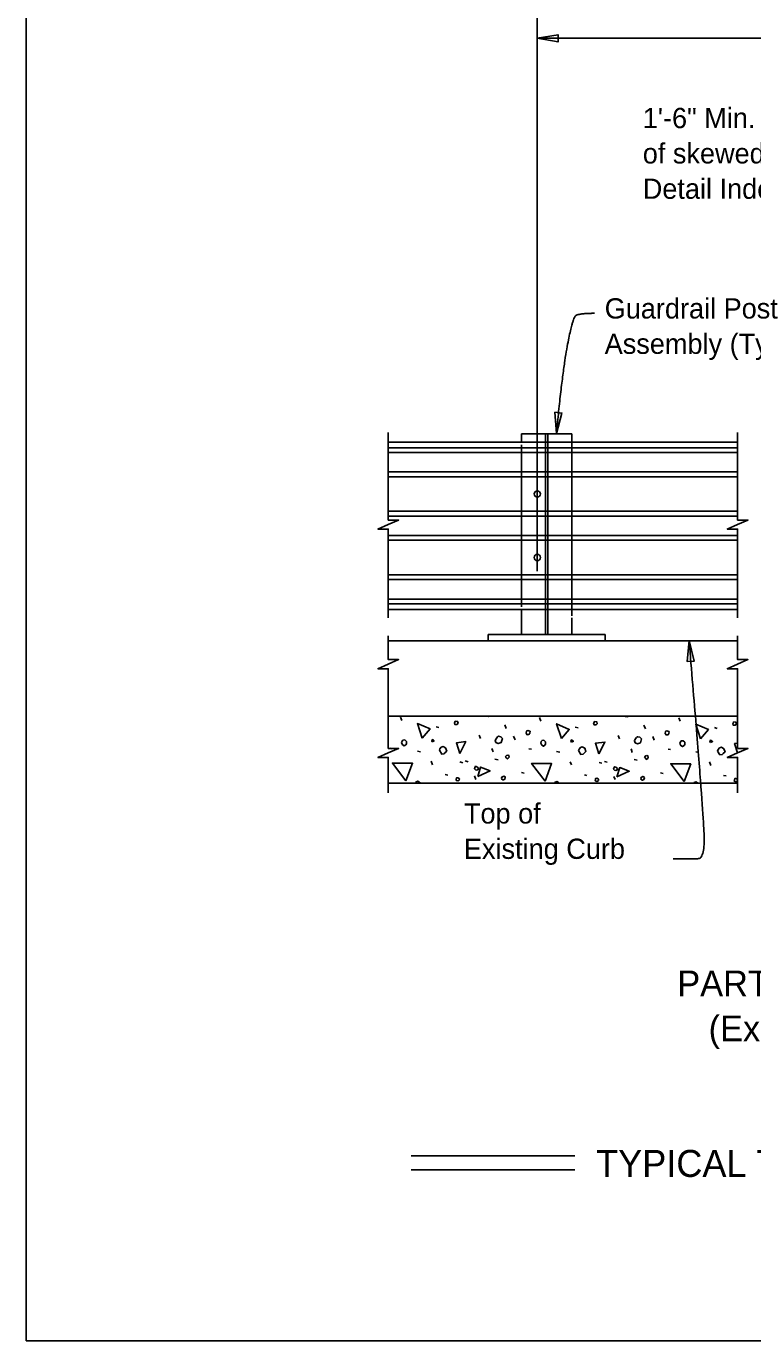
# Model space of a CAD drawing. Extents: x 0 to 41.1, y 0 to 25.9.
# Drawn here: x 0 to 7.23, y 0 to 13.09 of the extents above; entities that cross this region are included whole.
import ezdxf

# ---------------------------------------------------------------- set-up
doc = ezdxf.new("R2010")
doc.units = 0
for name, color, linetype in [('Dimension', 7, 'Continuous'), ('ExistSuperStruct', 7, 'Continuous'), ('Miscellaneous', 7, 'Continuous'), ('Miscellaneous1', 7, 'Continuous'), ('SteelMisc', 7, 'Continuous'), ('SteelMisc_h', 7, 'Continuous'), ('TextStructures', 7, 'Continuous')]:
    doc.layers.add(name, color=color, linetype=linetype)

msp = doc.modelspace()

# ---------------------------------------------------------------- linework, layer by layer
at = {"layer": 'Dimension'}
for p, q in [((5.085, 7.662), (5.085, 21.669)), ((5.459, 1.842), (3.831, 1.842)), ((5.459, 1.7), (3.831, 1.7))]:
    msp.add_line(p, q, dxfattribs=at)
for points in [[(5.085, 12.97), (11.216, 12.97), (11.216, 13.073), (11.261, 12.97), (11.306, 12.866), (11.306, 12.97), (17.272, 12.97)], [(3.602, 7.199), (3.602, 8.082), (3.499, 8.082), (3.602, 8.127), (3.705, 8.172), (3.602, 8.172), (3.602, 9.045)], [(7.079, 7.199), (7.079, 8.082), (6.976, 8.082), (7.079, 8.127), (7.182, 8.172), (7.079, 8.172), (7.079, 9.045)], [(3.602, 6.222), (3.602, 6.692), (3.499, 6.692), (3.602, 6.737), (3.705, 6.782), (3.602, 6.782), (3.602, 7.02)], [(7.079, 6.222), (7.079, 6.692), (6.976, 6.692), (7.079, 6.737), (7.182, 6.782), (7.079, 6.782), (7.079, 7.02)], [(3.602, 5.457), (3.602, 5.808), (3.499, 5.808), (3.602, 5.853), (3.705, 5.898), (3.602, 5.898), (3.602, 6.222)], [(7.079, 5.457), (7.079, 5.808), (6.976, 5.808), (7.079, 5.853), (7.182, 5.898), (7.079, 5.898), (7.079, 6.222)]]:
    msp.add_lwpolyline(points, dxfattribs=at)
for points in [[(5.085, 12.97), (5.293, 12.934), (5.293, 13.005)], [(5.275, 9.034), (5.33, 9.238), (5.26, 9.245)], [(6.596, 6.972), (6.578, 6.762), (6.648, 6.768)]]:
    msp.add_lwpolyline(points, close=True, dxfattribs=at)
for points in [[(5.654, 10.231), (5.491, 10.231), (5.438, 10.178), (5.34, 9.691), (5.275, 9.034)], [(6.439, 4.8), (6.622, 4.8), (6.746, 4.8), (6.746, 5.193), (6.596, 6.972)]]:
    msp.add_open_spline(points, degree=2, dxfattribs=at)
at = {"layer": 'ExistSuperStruct'}
for p, q in [((7.079, 6.97), (3.602, 6.97)), ((3.602, 6.22), (7.079, 6.22)), ((7.079, 5.553), (3.602, 5.553))]:
    msp.add_line(p, q, dxfattribs=at)
at = {"layer": 'Miscellaneous'}
for p, q in [((3.738, 6.175), (3.724, 6.21)), ((5.122, 6.171), (5.108, 6.207)), ((6.507, 6.168), (6.493, 6.203)), ((4.078, 6.112), (4.106, 6.105)), ((4.52, 5.996), (4.506, 6.031)), ((4.776, 6.096), (4.762, 6.132)), ((5.463, 6.109), (5.491, 6.102)), ((5.905, 5.992), (5.891, 6.027)), ((6.161, 6.093), (6.147, 6.128)), ((6.848, 6.105), (6.876, 6.098)), ((3.617, 5.899), (3.642, 5.895)), ((4.646, 5.863), (4.633, 5.897)), ((4.864, 5.984), (4.85, 6.019)), ((5.002, 5.895), (5.027, 5.892)), ((6.03, 5.859), (6.018, 5.893)), ((6.249, 5.98), (6.235, 6.016)), ((6.387, 5.892), (6.412, 5.888)), ((3.893, 5.871), (3.923, 5.865)), ((4.042, 5.736), (4.029, 5.77)), ((4.316, 5.763), (4.344, 5.756)), ((4.368, 5.773), (4.396, 5.766)), ((4.664, 5.791), (4.695, 5.786)), ((5.278, 5.867), (5.308, 5.862)), ((5.426, 5.733), (5.414, 5.766)), ((5.7, 5.759), (5.729, 5.752)), ((5.753, 5.769), (5.781, 5.762)), ((6.049, 5.788), (6.079, 5.782)), ((6.663, 5.864), (6.693, 5.858)), ((6.811, 5.729), (6.799, 5.763)), ((4.169, 5.637), (4.196, 5.632)), ((4.928, 5.659), (4.954, 5.653)), ((5.554, 5.634), (5.58, 5.629)), ((6.313, 5.655), (6.339, 5.65)), ((6.938, 5.63), (6.965, 5.625)), ((4.474, 5.59), (4.462, 5.624)), ((5.859, 5.587), (5.846, 5.62))]:
    msp.add_line(p, q, dxfattribs=at)
for points in [[(4.266, 6.137), (4.287, 6.137), (4.297, 6.148), (4.292, 6.167), (4.269, 6.169), (4.266, 6.158), (4.26, 6.149), (4.266, 6.137), (4.262, 6.141)], [(4.576, 6.22), (4.577, 6.218), (4.598, 6.215), (4.601, 6.22)], [(5.65, 6.133), (5.671, 6.133), (5.682, 6.144), (5.677, 6.164), (5.654, 6.165), (5.65, 6.155), (5.645, 6.146), (5.65, 6.133), (5.647, 6.137)], [(5.959, 6.22), (5.961, 6.215), (5.983, 6.211), (5.987, 6.22)], [(7.035, 6.13), (7.056, 6.13), (7.067, 6.141), (7.061, 6.16), (7.038, 6.162), (7.035, 6.151), (7.03, 6.142), (7.035, 6.13), (7.031, 6.133)], [(3.941, 6), (3.893, 6.146), (4.019, 6.092), (3.941, 6)], [(4.974, 6.051), (4.983, 6.035), (5.002, 6.037), (5.011, 6.049), (5.013, 6.069), (5, 6.074), (4.992, 6.076), (4.981, 6.072), (4.977, 6.069), (4.974, 6.051)], [(5.326, 5.996), (5.278, 6.143), (5.403, 6.088), (5.326, 5.996)], [(6.359, 6.047), (6.367, 6.032), (6.387, 6.033), (6.396, 6.046), (6.397, 6.065), (6.385, 6.07), (6.376, 6.072), (6.366, 6.069), (6.362, 6.065), (6.359, 6.047)], [(6.71, 5.993), (6.663, 6.139), (6.788, 6.085), (6.71, 5.993)], [(3.734, 5.956), (3.745, 5.934), (3.762, 5.924), (3.777, 5.934), (3.784, 5.945), (3.784, 5.966), (3.768, 5.982), (3.748, 5.98), (3.739, 5.971), (3.734, 5.956)], [(4.04, 5.964), (4.059, 5.973), (4.052, 5.98), (4.04, 5.986), (4.035, 5.973), (4.04, 5.964)], [(4.111, 5.88), (4.134, 5.842), (4.157, 5.844), (4.165, 5.853), (4.185, 5.872), (4.173, 5.903), (4.148, 5.917), (4.13, 5.91), (4.116, 5.895), (4.111, 5.88)], [(4.313, 5.849), (4.28, 5.953), (4.373, 5.966), (4.313, 5.849)], [(4.674, 5.958), (4.697, 5.946), (4.727, 5.958), (4.739, 5.996), (4.722, 6.013), (4.699, 6.019), (4.688, 6.012), (4.676, 5.992), (4.667, 5.976), (4.674, 5.958)], [(5.119, 5.952), (5.129, 5.931), (5.147, 5.92), (5.161, 5.931), (5.168, 5.941), (5.168, 5.963), (5.152, 5.979), (5.133, 5.977), (5.124, 5.968), (5.119, 5.952)], [(5.425, 5.961), (5.444, 5.97), (5.437, 5.977), (5.425, 5.982), (5.419, 5.97), (5.425, 5.961)], [(5.495, 5.876), (5.518, 5.839), (5.541, 5.841), (5.55, 5.849), (5.57, 5.869), (5.557, 5.899), (5.532, 5.913), (5.515, 5.906), (5.501, 5.892), (5.495, 5.876)], [(5.698, 5.845), (5.664, 5.95), (5.758, 5.962), (5.698, 5.845)], [(6.059, 5.955), (6.082, 5.943), (6.112, 5.955), (6.124, 5.992), (6.106, 6.01), (6.083, 6.015), (6.073, 6.008), (6.06, 5.989), (6.052, 5.973), (6.059, 5.955)], [(6.503, 5.948), (6.514, 5.927), (6.532, 5.917), (6.546, 5.927), (6.553, 5.938), (6.553, 5.959), (6.537, 5.975), (6.518, 5.973), (6.509, 5.964), (6.503, 5.948)], [(6.809, 5.957), (6.829, 5.966), (6.822, 5.973), (6.809, 5.979), (6.804, 5.966), (6.809, 5.957)], [(6.88, 5.872), (6.903, 5.835), (6.926, 5.837), (6.935, 5.846), (6.954, 5.865), (6.942, 5.895), (6.917, 5.91), (6.899, 5.903), (6.885, 5.888), (6.88, 5.872)], [(7.079, 5.853), (7.049, 5.946), (7.079, 5.95)], [(4.776, 5.804), (4.786, 5.793), (4.797, 5.8), (4.804, 5.811), (4.801, 5.828), (4.792, 5.83), (4.779, 5.828), (4.769, 5.818), (4.776, 5.804)], [(6.161, 5.8), (6.171, 5.789), (6.182, 5.796), (6.189, 5.807), (6.185, 5.825), (6.176, 5.827), (6.164, 5.825), (6.153, 5.814), (6.161, 5.8)], [(3.778, 5.575), (3.644, 5.752), (3.844, 5.751), (3.778, 5.575)], [(4.471, 5.684), (4.483, 5.683), (4.495, 5.688), (4.499, 5.699), (4.494, 5.707), (4.483, 5.715), (4.471, 5.72), (4.464, 5.706), (4.46, 5.695), (4.471, 5.684)], [(4.493, 5.62), (4.521, 5.712), (4.615, 5.674), (4.493, 5.62)], [(5.163, 5.572), (5.029, 5.749), (5.228, 5.747), (5.163, 5.572)], [(5.855, 5.681), (5.868, 5.679), (5.88, 5.684), (5.884, 5.695), (5.878, 5.704), (5.868, 5.711), (5.855, 5.716), (5.848, 5.702), (5.845, 5.692), (5.855, 5.681)], [(5.878, 5.616), (5.906, 5.708), (6, 5.671), (5.878, 5.616)], [(6.548, 5.568), (6.413, 5.745), (6.613, 5.743), (6.548, 5.568)], [(3.919, 5.553), (3.92, 5.554), (3.911, 5.563), (3.895, 5.572), (3.879, 5.567), (3.875, 5.553)], [(4.277, 5.579), (4.296, 5.574), (4.309, 5.583), (4.31, 5.595), (4.307, 5.598), (4.293, 5.606), (4.28, 5.604), (4.279, 5.591), (4.277, 5.579)], [(4.741, 5.584), (4.748, 5.584), (4.762, 5.591), (4.767, 5.607), (4.765, 5.616), (4.751, 5.623), (4.733, 5.613), (4.73, 5.602), (4.733, 5.591), (4.741, 5.584)], [(5.302, 5.553), (5.296, 5.56), (5.28, 5.568), (5.264, 5.563), (5.26, 5.553)], [(5.662, 5.575), (5.681, 5.57), (5.693, 5.579), (5.695, 5.591), (5.692, 5.595), (5.677, 5.602), (5.665, 5.6), (5.663, 5.588), (5.662, 5.575)], [(6.125, 5.581), (6.132, 5.581), (6.146, 5.588), (6.152, 5.604), (6.15, 5.613), (6.136, 5.62), (6.118, 5.609), (6.115, 5.598), (6.118, 5.588), (6.125, 5.581)], [(6.683, 5.553), (6.68, 5.556), (6.664, 5.565), (6.648, 5.56), (6.646, 5.553)], [(7.079, 5.589), (7.076, 5.591), (7.062, 5.598), (7.05, 5.597), (7.048, 5.584), (7.046, 5.572)], [(7.046, 5.572), (7.066, 5.567), (7.078, 5.575), (7.079, 5.582)]]:
    msp.add_lwpolyline(points, dxfattribs=at)
at = {"layer": 'Miscellaneous1'}
msp.add_lwpolyline([(0, 25.946), (41.051, 25.946), (41.051, 0), (0, 0)], close=True, dxfattribs=at)
at = {"layer": 'SteelMisc'}
for p, q in [((4.929, 9.032), (5.429, 9.032)), ((4.929, 9.032), (4.929, 8.949)), ((3.602, 8.949), (7.079, 8.949)), ((7.079, 8.893), (3.602, 8.893)), ((7.079, 8.845), (3.602, 8.845)), ((7.079, 8.652), (3.602, 8.652)), ((7.079, 8.604), (3.602, 8.604)), ((7.079, 8.26), (3.602, 8.26)), ((7.079, 8.212), (3.602, 8.212)), ((7.079, 8.019), (3.602, 8.019)), ((7.079, 7.971), (3.602, 7.971)), ((7.079, 7.627), (3.602, 7.627)), ((7.079, 7.579), (3.602, 7.579)), ((7.079, 7.386), (3.602, 7.386)), ((7.079, 7.338), (3.602, 7.338)), ((3.602, 7.282), (7.079, 7.282)), ((4.929, 7.282), (4.929, 7.032)), ((5.429, 7.199), (5.429, 7.032)), ((4.596, 7.032), (5.762, 7.032)), ((4.596, 6.97), (4.596, 7.032)), ((4.596, 6.97), (5.762, 6.97)), ((4.929, 7.032), (5.429, 7.032)), ((5.762, 7.032), (5.762, 6.97))]:
    msp.add_line(p, q, dxfattribs=at)
for centre in [(5.085, 8.432), (5.085, 7.799)]:
    msp.add_circle(centre, 0.0312, dxfattribs=at)
at = {"layer": 'SteelMisc_h'}
for p, q in [((5.168, 7.032), (5.168, 9.032)), ((5.189, 7.032), (5.189, 9.032)), ((5.429, 9.032), (5.429, 7.219)), ((4.929, 8.92), (4.929, 7.308))]:
    msp.add_line(p, q, dxfattribs=at)
at = {"layer": 'TextStructures'}
msp.add_lwpolyline([(0, 0), (41.051, 0), (41.051, 25.946), (0, 25.946)], close=True, dxfattribs=at)

# ---------------------------------------------------------------- texts
at = {"layer": 'Dimension'}
for s, height, p in [('1\'-6" Min. for non skewed joints.  For treatment ', 0.2016, (6.135, 12.075)), ('of skewed Intermediate Deck Joints see Skew ', 0.2016, (6.135, 11.723)), ('Detail Index 460-470, Sheet 2 (Typ.)', 0.2016, (6.135, 11.371)), ('Guardrail Post ', 0.2016, (5.756, 10.179)), ('Assembly (Typ.)', 0.2016, (5.756, 9.827)), ('Top of ', 0.2016, (4.355, 5.15)), ('Existing Curb', 0.2016, (4.355, 4.798)), ('PARTIAL ELEVATION OF INSIDE FACE OF RAILING', 0.256, (6.478, 3.43)), ('(Existing Traffic Railing not shown for clarity)', 0.256, (6.79, 2.982))]:
    msp.add_text(s, height=height, dxfattribs=at).set_placement(p)
at = {"layer": 'TextStructures'}
msp.add_text('TYPICAL TREATMENT OF RAILING ALONG BRIDGE', height=0.2688, dxfattribs=at).set_placement((5.67, 1.631))

doc.saveas('drawing.dxf')
